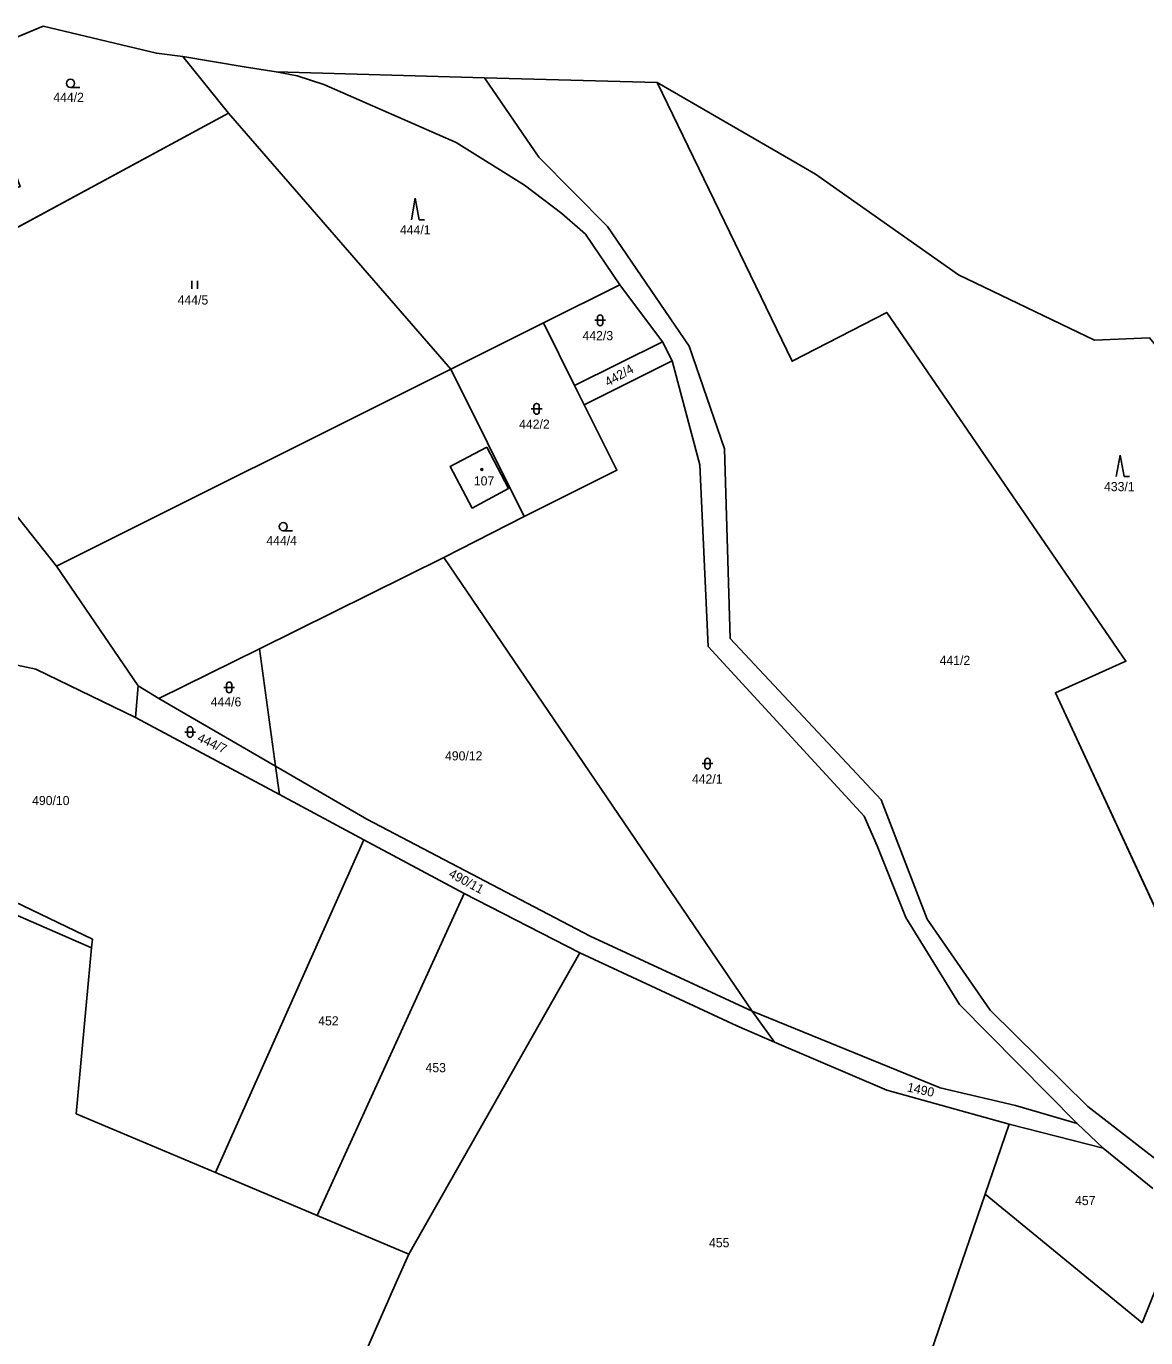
# Model space of a CAD drawing. Extents: x -760642 to -757221, y -1092371 to -1088855.
# Drawn here: x -760176.2 to -759968, y -1089492.6 to -1089248.6 of the extents above; entities that cross this region are included whole.
import ezdxf

# ---------------------------------------------------------------- set-up
doc = ezdxf.new("R2010")
doc.units = 0
for name, color, linetype in [('Vrstva 1', 7, 'Continuous'), ('Vrstva 13', 7, 'Continuous'), ('Vrstva 18', 7, 'Continuous'), ('Vrstva 19', 7, 'Continuous'), ('Vrstva 25', 7, 'Continuous'), ('Vrstva 30', 7, 'Continuous')]:
    doc.layers.add(name, color=color, linetype=linetype)

msp = doc.modelspace()

# ---------------------------------------------------------------- linework, layer by layer
at = {"layer": 'Vrstva 1'}
for p, q in [((-760138.6, -1089264.79), (-760147.13, -1089254.29)), ((-760125.85, -1089257.89), (-760129.72, -1089257.15)), ((-760120.86, -1089259.48), (-760125.85, -1089257.89)), ((-760080.91, -1089273), (-760090.98, -1089258.23)), ((-760096.25, -1089270.29), (-760120.86, -1089259.48)), ((-760058.9, -1089259.13), (-760033.79, -1089310.97)), ((-760185.74, -1089290.3), (-760138.6, -1089264.79)), ((-760097.26, -1089312.43), (-760138.6, -1089264.79)), ((-760083.55, -1089278.2), (-760096.25, -1089270.29)), ((-760080.91, -1089273), (-760068.09, -1089285.87)), ((-760076.62, -1089283.5), (-760083.55, -1089278.2)), ((-760072.19, -1089287.34), (-760076.62, -1089283.5)), ((-760072.19, -1089287.34), (-760065.82, -1089296.74)), ((-760068.09, -1089285.87), (-760052.92, -1089308.16)), ((-760080.03, -1089303.83), (-760065.82, -1089296.74)), ((-760065.82, -1089296.74), (-760057.9, -1089307.32)), ((-760033.79, -1089310.97), (-760016.19, -1089301.87)), ((-760016.19, -1089301.87), (-759971.69, -1089366.76)), ((-760097.26, -1089312.43), (-760080.03, -1089303.83)), ((-760080.03, -1089303.83), (-760074.23, -1089315.47)), ((-760074.23, -1089315.47), (-760057.9, -1089307.32)), ((-760057.9, -1089307.32), (-760056.11, -1089310.89)), ((-760052.92, -1089308.16), (-760046.38, -1089327.26)), ((-760072.44, -1089319.05), (-760056.11, -1089310.89)), ((-760056.11, -1089310.89), (-760050.93, -1089330.22)), ((-760170.63, -1089349.04), (-760097.26, -1089312.43)), ((-760083.6, -1089339.81), (-760097.26, -1089312.43)), ((-760074.23, -1089315.47), (-760072.44, -1089319.05)), ((-760072.44, -1089319.05), (-760066.37, -1089331.21)), ((-760097.39, -1089330.56), (-760090.57, -1089326.91)), ((-760090.57, -1089326.91), (-760086.53, -1089334.6)), ((-760046.38, -1089327.26), (-760045.31, -1089362.5)), ((-760093.26, -1089338.28), (-760097.39, -1089330.56)), ((-760066.37, -1089331.21), (-760083.6, -1089339.81)), ((-760050.93, -1089330.22), (-760049.41, -1089364)), ((-760086.53, -1089334.6), (-760093.26, -1089338.28)), ((-760180.04, -1089337.19), (-760170.63, -1089349.04)), ((-760098.54, -1089347.46), (-760083.6, -1089339.81)), ((-760132.82, -1089364.42), (-760098.54, -1089347.46)), ((-760098.54, -1089347.46), (-760041.19, -1089431.85)), ((-760170.63, -1089349.04), (-760155.4, -1089371.31)), ((-760045.31, -1089362.5), (-760017.21, -1089392.54)), ((-760174.42, -1089368.23), (-760193.66, -1089364.22)), ((-760151.54, -1089373.67), (-760132.82, -1089364.42)), ((-760132.82, -1089364.42), (-760129.86, -1089386.27)), ((-760049.41, -1089364), (-760020.35, -1089395.54)), ((-760174.42, -1089368.23), (-760155.88, -1089377.23)), ((-759971.69, -1089366.76), (-759984.79, -1089372.63)), ((-760155.4, -1089371.31), (-760155.88, -1089377.23)), ((-760155.4, -1089371.31), (-760151.54, -1089373.67)), ((-759984.79, -1089372.63), (-759957.08, -1089432.43)), ((-760151.54, -1089373.67), (-760129.86, -1089386.27)), ((-760155.88, -1089377.23), (-760129.14, -1089391.55)), ((-760129.86, -1089386.27), (-760112.87, -1089396.11)), ((-760129.86, -1089386.27), (-760129.14, -1089391.55)), ((-760129.14, -1089391.55), (-760113.45, -1089399.95)), ((-760017.21, -1089392.54), (-760008.68, -1089414.75)), ((-760112.87, -1089396.11), (-760071.37, -1089417.91)), ((-760020.35, -1089395.54), (-760017.99, -1089401.11)), ((-760203.83, -1089399.31), (-760163.92, -1089418.42)), ((-760113.45, -1089399.95), (-760141.04, -1089461.84)), ((-760113.45, -1089399.95), (-760094.75, -1089409.93)), ((-760017.99, -1089401.11), (-760012.61, -1089414.41)), ((-760122.09, -1089469.83), (-760094.75, -1089409.93)), ((-760094.75, -1089409.93), (-760073.25, -1089420.98)), ((-760012.61, -1089414.41), (-760002.62, -1089430.61)), ((-760008.68, -1089414.75), (-759996.94, -1089431.68)), ((-760164.07, -1089420.04), (-760163.92, -1089418.42)), ((-760071.37, -1089417.91), (-760041.19, -1089431.85)), ((-760105.07, -1089477.01), (-760073.25, -1089420.98)), ((-760073.25, -1089420.98), (-760044.05, -1089434.58)), ((-760041.19, -1089431.85), (-760006.26, -1089446.11)), ((-760041.19, -1089431.85), (-760037.07, -1089437.58)), ((-760002.62, -1089430.61), (-759980.73, -1089452.73)), ((-759996.94, -1089431.68), (-759978.78, -1089449.57)), ((-760044.05, -1089434.58), (-760037.07, -1089437.58)), ((-760037.07, -1089437.58), (-760016.19, -1089446.56)), ((-760006.26, -1089446.11), (-759992.26, -1089449.4)), ((-759993.39, -1089452.84), (-760016.19, -1089446.56)), ((-759992.26, -1089449.4), (-759980.73, -1089452.73)), ((-759978.78, -1089449.57), (-759958.75, -1089465.1)), ((-759993.39, -1089452.84), (-759997.87, -1089465.91)), ((-759975.9, -1089457.33), (-759993.39, -1089452.84)), ((-759980.73, -1089452.73), (-759975.9, -1089457.33)), ((-759975.9, -1089457.33), (-759966.67, -1089464.85)), ((-759997.87, -1089465.91), (-760007.96, -1089495.36)), ((-759997.87, -1089465.91), (-759968.7, -1089489.82)), ((-759968.7, -1089489.82), (-759960.18, -1089468.67))]:
    msp.add_line(p, q, dxfattribs=at)
at = {"layer": 'Vrstva 13'}
for p, q in [((-760191.2, -1089256.2), (-760173.06, -1089248.64)), ((-760173.06, -1089248.64), (-760152.03, -1089253.67)), ((-760152.03, -1089253.67), (-760147.13, -1089254.29)), ((-760147.13, -1089254.29), (-760135.7, -1089256.17)), ((-760135.7, -1089256.17), (-760129.72, -1089257.15)), ((-760129.72, -1089257.15), (-760090.98, -1089258.23)), ((-760090.98, -1089258.23), (-760058.9, -1089259.13)), ((-760058.9, -1089259.13), (-760038.75, -1089270.77)), ((-760038.75, -1089270.77), (-760032.85, -1089274.17)), ((-760032.85, -1089274.17), (-760029.43, -1089276.14)), ((-760029.43, -1089276.14), (-760002.84, -1089294.87)), ((-760002.84, -1089294.87), (-759977.53, -1089307.06)), ((-759977.53, -1089307.06), (-759967.3, -1089306.61)), ((-760164.07, -1089420.04), (-760210.72, -1089399.87)), ((-760164.07, -1089420.04), (-760164.7, -1089426.75)), ((-760164.7, -1089426.75), (-760166.96, -1089450.91)), ((-760141.04, -1089461.84), (-760166.96, -1089450.91)), ((-760122.09, -1089469.83), (-760141.04, -1089461.84)), ((-760105.07, -1089477.01), (-760122.09, -1089469.83)), ((-760107.41, -1089482.32), (-760105.07, -1089477.01)), ((-760113.5, -1089496.15), (-760107.41, -1089482.32))]:
    msp.add_line(p, q, dxfattribs=at)
at = {"layer": 'Vrstva 25'}
for p, q in [((-760166.25, -1089260.01), (-760168, -1089260.01)), ((-760103.862, -1089280.639), (-760104.595, -1089284.639)), ((-760103.862, -1089280.639), (-760103.129, -1089284.639)), ((-760103.129, -1089284.639), (-760102.129, -1089284.639)), ((-760145.417, -1089295.975), (-760145.417, -1089297.475)), ((-760144.395, -1089297.475), (-760144.395, -1089295.975)), ((-760070.49, -1089303.34), (-760068.49, -1089303.34)), ((-760069.99, -1089303.84), (-760069.99, -1089302.84)), ((-760068.99, -1089303.84), (-760068.99, -1089302.84)), ((-760081.8, -1089320.31), (-760081.8, -1089319.31)), ((-760080.8, -1089320.31), (-760080.8, -1089319.31)), ((-760082.3, -1089319.81), (-760080.3, -1089319.81)), ((-759972.742, -1089328.409), (-759973.475, -1089332.409)), ((-759972.742, -1089328.409), (-759972.009, -1089332.409)), ((-759972.009, -1089332.409), (-759971.009, -1089332.409)), ((-760126.69, -1089342.47), (-760128.44, -1089342.47)), ((-760139.49, -1089371.63), (-760137.49, -1089371.63)), ((-760138.99, -1089372.13), (-760138.99, -1089371.13)), ((-760137.99, -1089372.13), (-760137.99, -1089371.13)), ((-760146.76, -1089379.92), (-760144.76, -1089379.92)), ((-760146.26, -1089380.42), (-760146.26, -1089379.42)), ((-760145.26, -1089380.42), (-760145.26, -1089379.42)), ((-760050.02, -1089386.3), (-760050.02, -1089385.3)), ((-760049.02, -1089386.3), (-760049.02, -1089385.3)), ((-760050.52, -1089385.8), (-760048.52, -1089385.8))]:
    msp.add_line(p, q, dxfattribs=at)
for centre, radius in [((-760168, -1089259.26), 0.75), ((-760091.5, -1089331.1), 0.175), ((-760128.44, -1089341.72), 0.75)]:
    msp.add_circle(centre, radius, dxfattribs=at)
for centre, start, end in [((-760069.49, -1089302.84), 0, 180), ((-760069.49, -1089303.84), 180, 0), ((-760081.3, -1089319.31), 0, 180), ((-760081.3, -1089320.31), 180, 0), ((-760138.49, -1089371.13), 0, 180), ((-760138.49, -1089372.13), 180, 0), ((-760145.76, -1089379.42), 0, 180), ((-760145.76, -1089380.42), 180, 0), ((-760049.52, -1089385.3), 0, 180), ((-760049.52, -1089386.3), 180, 0)]:
    msp.add_arc(centre, 0.5, start, end, dxfattribs=at)
at = {"layer": 'Vrstva 30'}
for points in [[(-760186.58, -1089263.55), (-760183.76, -1089267.86), (-760182.74, -1089267.19), (-760181.58, -1089268.96), (-760181.33, -1089268.79), (-760179.48, -1089271.6), (-760180.74, -1089272.45), (-760179.02, -1089275.14), (-760178.66, -1089274.9), (-760177.38, -1089278.47), (-760184.82, -1089281.01), (-760183.98, -1089282.18), (-760189, -1089285.46), (-760185.74, -1089290.3), (-760138.6, -1089264.79), (-760147.13, -1089254.29), (-760152.03, -1089253.67), (-760173.06, -1089248.64), (-760191.2, -1089256.2), (-760186.58, -1089263.55)], [(-760147.13, -1089254.29), (-760138.6, -1089264.79), (-760097.26, -1089312.43), (-760080.03, -1089303.83), (-760065.82, -1089296.74), (-760072.19, -1089287.34), (-760076.62, -1089283.5), (-760083.55, -1089278.2), (-760096.25, -1089270.29), (-760120.86, -1089259.48), (-760125.85, -1089257.89), (-760129.72, -1089257.15), (-760135.7, -1089256.17), (-760147.13, -1089254.29)], [(-759944.6, -1089399.86), (-759943.63, -1089397.92), (-759938.89, -1089392.94), (-759950.38, -1089338.52), (-759953.92, -1089334), (-759955.01, -1089321.48), (-759967.3, -1089306.61), (-759977.53, -1089307.06), (-760002.84, -1089294.87), (-760029.43, -1089276.14), (-760032.85, -1089274.17), (-760038.75, -1089270.77), (-760058.9, -1089259.13), (-760033.79, -1089310.97), (-760016.19, -1089301.87), (-759971.69, -1089366.76), (-759984.79, -1089372.63), (-759957.08, -1089432.43), (-759956.67, -1089420.21), (-759955.67, -1089418.71), (-759944.6, -1089399.86)], [(-760065.82, -1089296.74), (-760080.03, -1089303.83), (-760074.23, -1089315.47), (-760057.9, -1089307.32), (-760065.82, -1089296.74)], [(-760080.03, -1089303.83), (-760097.26, -1089312.43), (-760083.6, -1089339.81), (-760066.37, -1089331.21), (-760072.44, -1089319.05), (-760074.23, -1089315.47), (-760080.03, -1089303.83)], [(-760072.44, -1089319.05), (-760056.11, -1089310.89), (-760057.9, -1089307.32), (-760074.23, -1089315.47), (-760072.44, -1089319.05)], [(-760083.6, -1089339.81), (-760097.26, -1089312.43), (-760170.63, -1089349.04), (-760155.4, -1089371.31), (-760151.54, -1089373.67), (-760132.82, -1089364.42), (-760098.54, -1089347.46), (-760083.6, -1089339.81)], [(-760090.57, -1089326.91), (-760097.39, -1089330.56), (-760093.26, -1089338.28), (-760086.53, -1089334.6), (-760090.57, -1089326.91)]]:
    msp.add_lwpolyline(points, dxfattribs=at)

# ---------------------------------------------------------------- texts
at = {"layer": 'Vrstva 18'}
for s, p in [('444/2', (-760171.194, -1089262.71)), ('444/1', (-760106.72, -1089287.35)), ('444/5', (-760148.07, -1089300.41)), ('442/3', (-760072.76, -1089307.04)), ('442/2', (-760084.559, -1089323.51)), ('433/1', (-759975.76, -1089335.12)), ('444/4', (-760131.569, -1089345.17)), ('441/2', (-760006.34, -1089367.44)), ('444/6', (-760141.92, -1089375.16)), ('490/12', (-760098.34, -1089385.2)), ('442/1', (-760052.41, -1089389.5)), ('490/10', (-760175.14, -1089393.51)), ('452', (-760121.92, -1089434.49)), ('453', (-760101.96, -1089443.19)), ('457', (-759981.15, -1089467.92)), ('455', (-760049.24, -1089475.76))]:
    msp.add_text(s, height=1.7, dxfattribs=at).set_placement(p)
for s, rotation, p in [('442/4', 29.53044, (-760068.022, -1089315.705)), ('444/7', 335.04975, (-760144.57, -1089381.58)), ('490/11', 331.41528, (-760097.81, -1089406.76)), ('1490', 347.90526, (-760012.494, -1089446.751))]:
    msp.add_text(s, height=1.7, rotation=rotation, dxfattribs=at).set_placement(p)
at = {"layer": 'Vrstva 19'}
msp.add_text('107', height=1.7, dxfattribs=at).set_placement((-760092.975, -1089334.06))

doc.saveas('drawing.dxf')
